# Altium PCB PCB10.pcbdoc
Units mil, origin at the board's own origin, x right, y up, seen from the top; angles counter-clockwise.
Board outline 2226.25 x 1287.2 mil, 2 copper layers (Top Layer, Bottom Layer); 3 components, 4 nets, 26 pads, 0 vias.
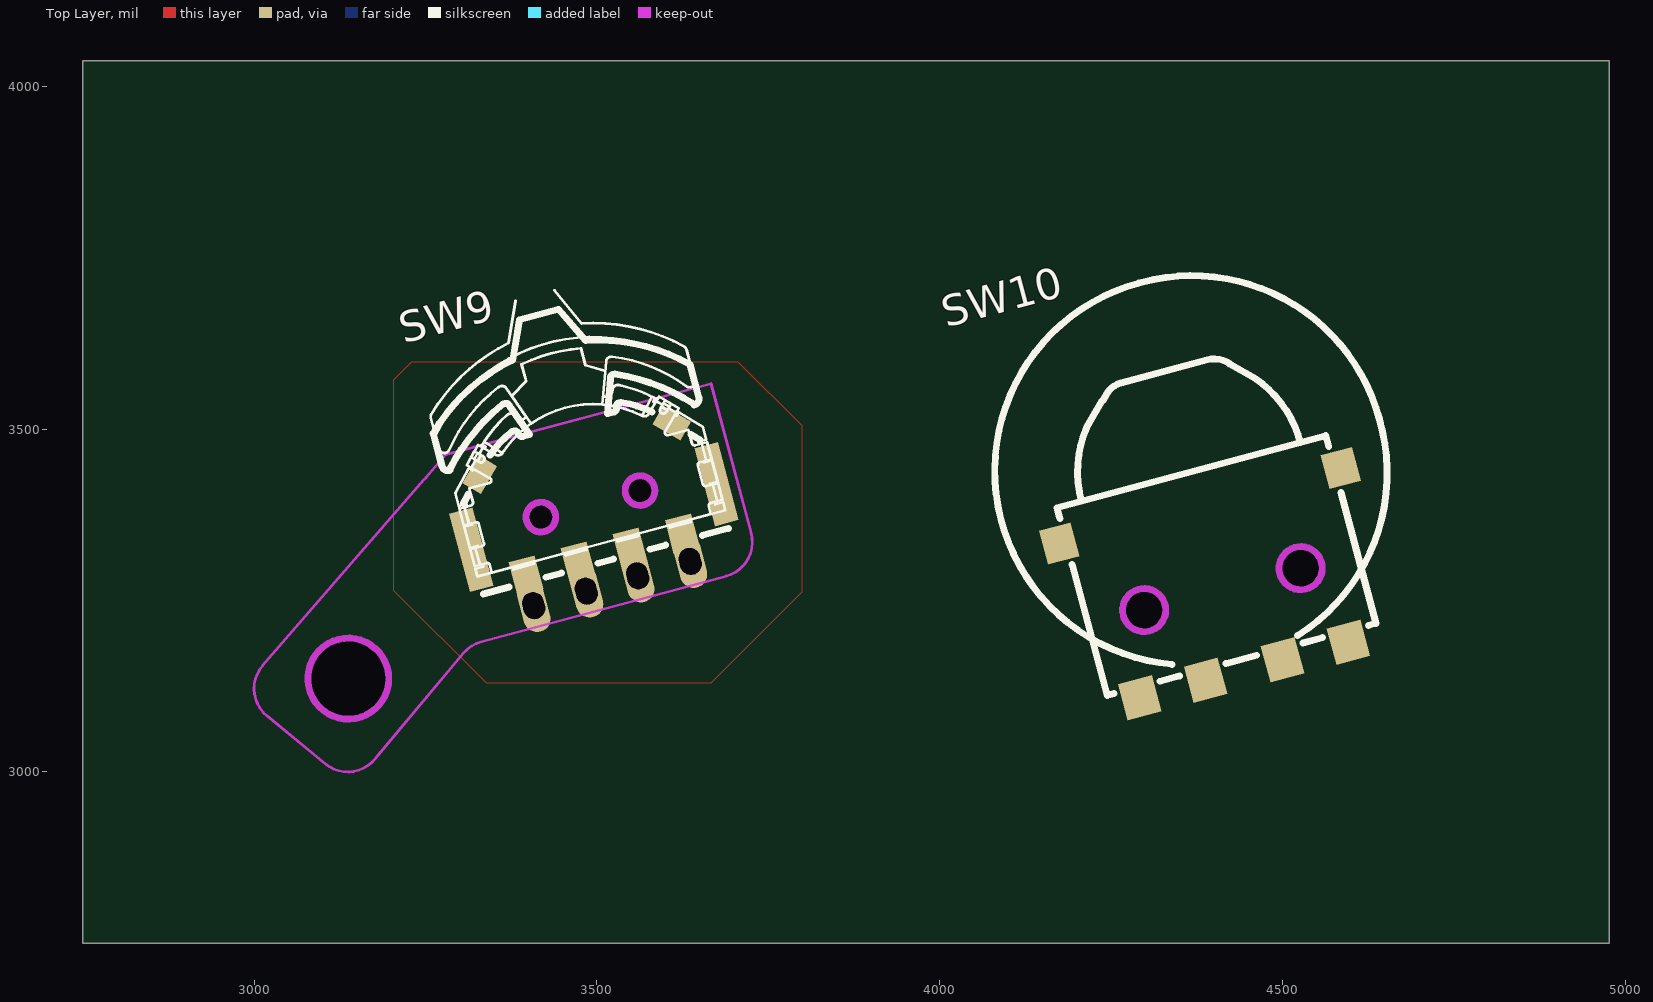
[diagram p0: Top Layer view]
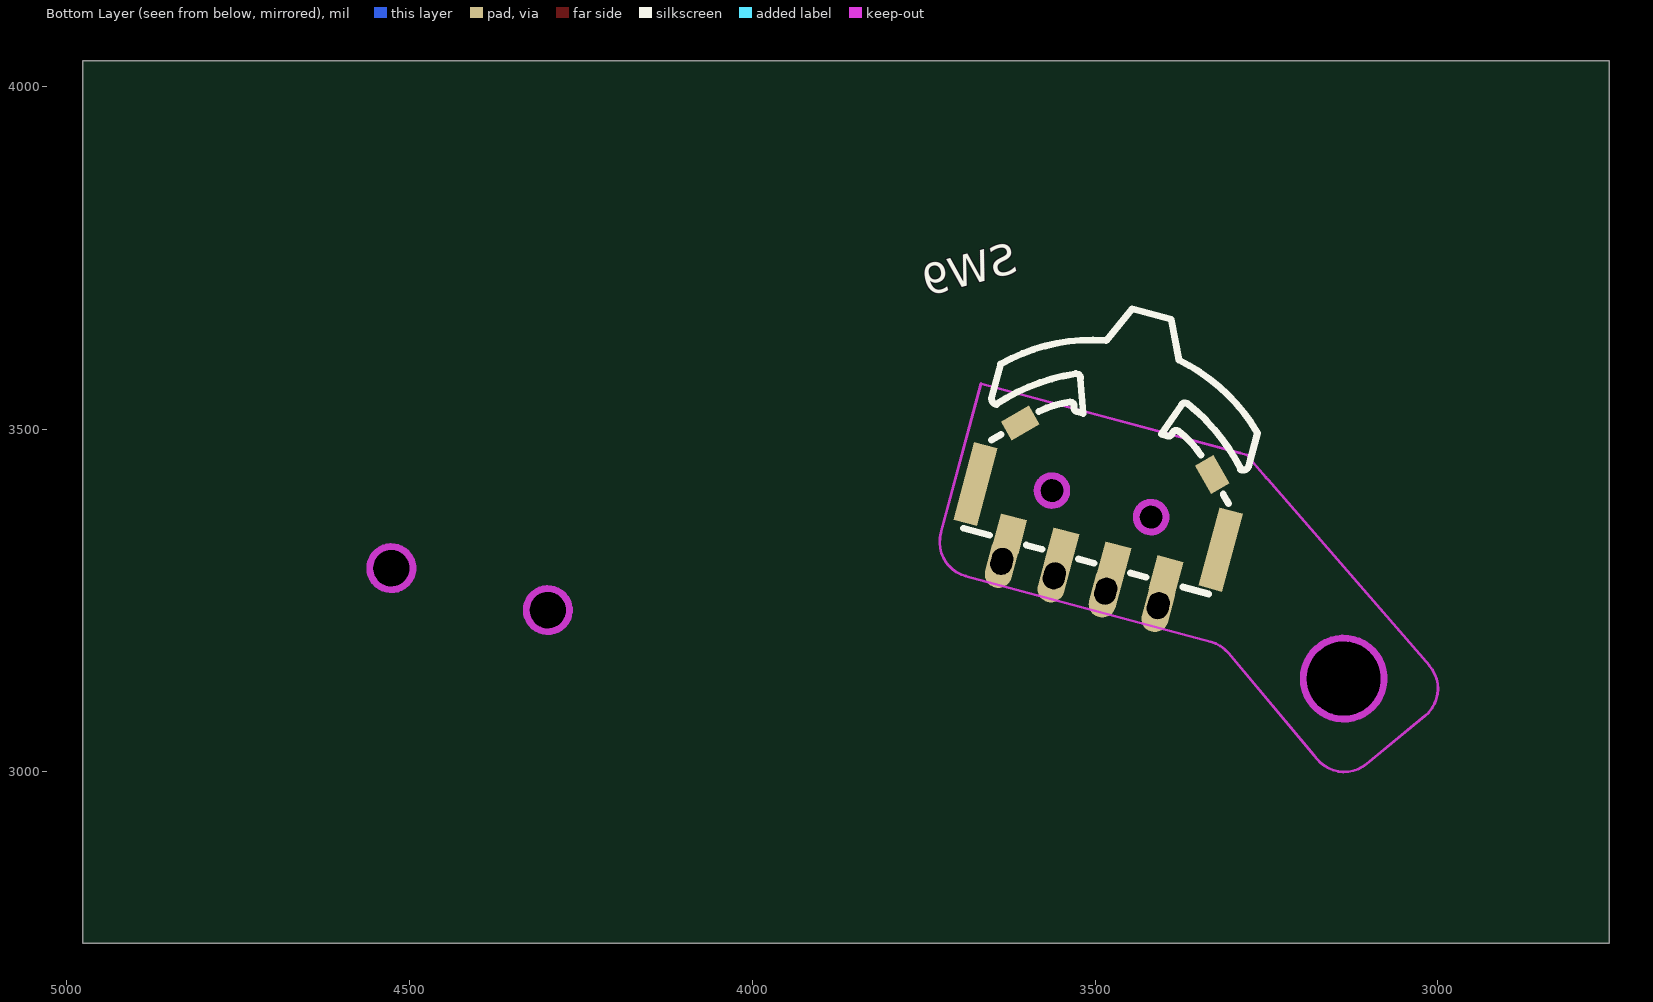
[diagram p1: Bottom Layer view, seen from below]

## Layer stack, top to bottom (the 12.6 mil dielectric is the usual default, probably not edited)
Top Layer: signal copper (thickness not stored)
Dielectric: dielectric 12.6, FR-4, Dk 4.8
Bottom Layer: signal copper (thickness not stored)

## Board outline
4976.25,2750 2750,2750 2750,4037.2 4976.25,4037.2
cut-out: 3196.46,3136.05 ccw(c3137.4,3135.79) 3078.35,3136.05 ccw(c3137.4,3136.31)

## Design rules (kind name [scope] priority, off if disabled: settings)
BoardOutlineClearance copperThickness1oz [All] p0: genericclearance=10 ignorepadtopadclearanceinfootprint=FALSE except(0: Arc-SplitContinuation Track-SplitContinuation SMDPad-SplitContinuation THPad-SplitContinuation Via-SplitContinuation Fill-SplitContinuation Poly-SplitContinuation Region-SplitContinuation Text-SplitContinuation; 6: SMDPad-CutoutEdge THPad-CutoutEdge Via-CutoutEdge Fill-CutoutEdge Region-CutoutEdge; 11.8: Track-OutlineEdge SMDPad-OutlineEdge THPad-OutlineEdge Via-OutlineEdge Fill-OutlineEdge Region-OutlineEdge Poly-OutlineEdge Text-OutlineEdge Track-CutoutEdge)
BoardOutlineClearance copperThickness2oz [All] p0: genericclearance=10 ignorepadtopadclearanceinfootprint=FALSE except(0: Arc-SplitContinuation Track-SplitContinuation SMDPad-SplitContinuation THPad-SplitContinuation Via-SplitContinuation Fill-SplitContinuation Poly-SplitContinuation Region-SplitContinuation Text-SplitContinuation; 6: SMDPad-CutoutEdge THPad-CutoutEdge Via-CutoutEdge Fill-CutoutEdge Region-CutoutEdge; 11.8: Track-OutlineEdge SMDPad-OutlineEdge THPad-OutlineEdge Via-OutlineEdge Fill-OutlineEdge Region-OutlineEdge Poly-OutlineEdge Text-OutlineEdge Track-CutoutEdge)
Clearance copperThickness1oz [(InNet('B5') OR InNet('GND') OR InNet('B3') OR InNet('B4'))] p1: gap=7 ignorepadtopadclearanceinfootprint=FALSE except(4: Track-Track; 6: Track-SMDPad SMDPad-SMDPad Track-THPad SMDPad-THPad THPad-THPad Track-Via SMDPad-Via THPad-Via Via-Via Track-Fill SMDPad-Fill THPad-Fill Via-Fill Fill-Fill SMDPad-Region THPad-Region Via-Region Fill-Region Region-Region Track-Poly SMDPad-Poly THPad-Poly Via-Poly Fill-Poly Poly-Poly Track-Text SMDPad-Text THPad-Text Via-Text Fill-Text Region-Text Poly-Text Text-Text Track-Hole SMDPad-Hole THPad-Hole Via-Hole Fill-Hole Region-Hole Poly-Hole Text-Hole; 11.8: Track-Region Region-Poly Track-Sheet SMDPad-Sheet THPad-Sheet Via-Sheet Fill-Sheet Region-Sheet Poly-Sheet Text-Sheet Sheet-Hole)
Clearance copperThickness2oz [All] p1: gap=7 ignorepadtopadclearanceinfootprint=FALSE except(6: Track-SMDPad SMDPad-SMDPad Track-THPad SMDPad-THPad THPad-THPad Track-Via SMDPad-Via THPad-Via Via-Via Track-Fill SMDPad-Fill THPad-Fill Via-Fill Fill-Fill SMDPad-Region THPad-Region Via-Region Fill-Region Region-Region Track-Poly SMDPad-Poly THPad-Poly Via-Poly Fill-Poly Poly-Poly Track-Text SMDPad-Text THPad-Text Via-Text Fill-Text Region-Text Poly-Text Text-Text Track-Hole SMDPad-Hole THPad-Hole Via-Hole Fill-Hole Region-Hole Poly-Hole Text-Hole; 8: Track-Track; 11.8: Track-Region Region-Poly Track-Sheet SMDPad-Sheet THPad-Sheet Via-Sheet Fill-Sheet Region-Sheet Poly-Sheet Text-Sheet Sheet-Hole)
DiffPairsRouting differentialPair [All] p1: maxuncoupledlength=10 minlimit=5.9843 maxlimit=5.9843 mostfreqgap=5.9843 toplayer_minwidth=5 toplayer_prefwidth=10 toplayer_maxwidth=100 bottomlayer_minwidth=5 bottomlayer_prefwidth=10 bottomlayer_maxwidth=100
PasteMaskExpansion pasteMaskExpansion [All] p1: expansion=0
PlaneConnect innerPlane [All] p1: planeconnectstyle=Relief reliefexpansion=20 reliefentries=4 reliefconductorwidth=10 reliefairgap=10
PolygonConnect copperRegion [All] p1: connectstyle=Direct reliefentries=4 reliefconductorwidth=10 polygonreliefangle="90 Angle" airgapwidth=10
RoutingVias viaSize [All] p1: viastyle="Through Hole" holewidth=12.0078 minholewidth=11.811 maxholewidth=248.0314 width=24.0158 minwidth=19.685 maxwidth=393.7008
SolderMaskExpansion solderMaskExpansion [All] p1: useseparateexpansions=TRUE expansion=2.0079 expansionbottom=2.0079
Width copperThickness1oz [All] p1: maxlimit=100 minlimit=5 preferedwidth=10
Width copperThickness2oz [All] p1: maxlimit=100 minlimit=8 preferedwidth=10

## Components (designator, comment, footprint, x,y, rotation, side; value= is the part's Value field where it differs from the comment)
SW9 "TM-2023" SW-SMD_TM-2023-1 3489.66,3393.93 r15 top
SW9 "TM-2023" SW-SMD_TM-2023-1 3489.68,3394 r195 bottom
SW10 "SIQ-02FVS3_2" SW-SMD_SIQ-02FVS3 4411.47,3268.43 r15 top

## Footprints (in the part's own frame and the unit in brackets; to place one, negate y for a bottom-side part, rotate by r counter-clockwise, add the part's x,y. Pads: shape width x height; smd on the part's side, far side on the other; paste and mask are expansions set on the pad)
SW-SMD_SIQ-02FVS3 [mm]
  rect 1.2x1.3 smd: 1(-5.4,3.15) 2(5.4,3.15)
  rect 1.3x1.4 smd: A(-4,-3.15) B(4,-3.15) C(1.475,-3.15) S(-1.475,-3.15)
  Board Outline Layer circle w0.005: c-3,-0.05 r0.8
  Board Outline Layer circle w0.005: c3,-0.05 r0.8
  Board Outline Layer circle w0.254: c-3,-0.05 r0.8
  Board Outline Layer circle w0.254: c3,-0.05 r0.8
  Multi-Layer board cut-out: -2.227,-0.257 -2.214,0.099 -2.356,0.425 -2.626,0.657 -2.97,0.749 -3.32,0.683 -3.606,0.472 -3.773,0.157 -3.773,0.157 -3.786,-0.199 -3.644,-0.525 -3.374,-0.757 -3.03,-0.85 -2.68,-0.783 -2.394,-0.572 -2.227,-0.257
  Multi-Layer board cut-out: 3.773,-0.257 3.786,0.099 3.644,0.425 3.374,0.657 3.03,0.749 2.68,0.683 2.393,0.472 2.227,0.157 2.227,0.157 2.227,-0.257 2.434,-0.616 2.793,-0.823 3.207,-0.823 3.566,-0.616 3.773,-0.257
  silkscreen extent -7.25,-2.75 7.25,11.7
SW-SMD_TM-2023-1 [mm]
  rect 1x1.3 smd: 1(-3,-2.03) 2(3,-2.03) C(-1,-2.03) T(1,-2.03)
  rect 0.9x3 smd: 3(-4.7,-0.58) 4(4.7,-0.58)
  rect 1.2x0.8 smd rot 135: 5(3.68,2.03)
  rect 1.2x0.8 smd rot 45: 6(-3.68,2.03)
  Board Outline Layer circle w0.005: c-1.9,-0.08 r0.55
  Board Outline Layer circle w0.005: c1.9,-0.08 r0.55
  Board Outline Layer circle w0.254: c-1.9,-0.08 r0.55
  Board Outline Layer circle w0.254: c1.9,-0.08 r0.55
  Multi-Layer board cut-out: -1.369,-0.223 -1.369,0.062 -1.511,0.309 -1.758,0.451 -2.043,0.451 -2.289,0.309 -2.431,0.062 -2.431,0.062 -2.441,-0.182 -2.343,-0.407 -2.157,-0.567 -1.921,-0.63 -1.68,-0.584 -1.483,-0.439 -1.369,-0.223
  Multi-Layer board cut-out: 2.431,-0.223 2.44,0.022 2.342,0.246 2.157,0.406 1.92,0.469 1.68,0.424 1.483,0.279 1.368,0.062 1.368,0.062 1.368,-0.223 1.511,-0.469 1.757,-0.612 2.042,-0.612 2.289,-0.469 2.431,-0.223
  silkscreen extent -4.95,-2.28 4.9,7.19

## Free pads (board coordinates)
  oval 78.74x39.37 hole 31.5 slot 39.37 at 105 deg rot 105: 9(3407.72,3242.53) 9(3484.39,3263.6) 9(3559.31,3285.84) 9(3635.98,3306.91)

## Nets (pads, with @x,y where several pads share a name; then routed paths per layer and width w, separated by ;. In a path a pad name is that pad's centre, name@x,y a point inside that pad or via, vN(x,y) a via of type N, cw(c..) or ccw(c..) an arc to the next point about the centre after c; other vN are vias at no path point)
B3: pad.9@3407.72,3242.53 SW9.1@3396.26,3286.16 SW9.2@3396.28,3286.22
B4: pad.9@3635.98,3306.91 SW9.1@3624.45,3347.36 SW9.2@3624.43,3347.3
B5: pad.9@3559.31,3285.84 SW9.C@3548.41,3326.99 SW9.T@3548.36,3326.91
GND: pad.9@3484.39,3263.6 SW9.3 SW9.4 SW9.5 SW9.6 SW9.C@3472.31,3306.53 SW9.T@3472.35,3306.61
pads on no net: SW10.1 SW10.2 SW10.A SW10.B SW10.C SW10.S

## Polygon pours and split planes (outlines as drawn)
GND on Top Layer (solid, remove dead copper, pour order 0): 3203.18,3571.4 3203.18,3265 3338.38,3129.81 3666.72,3129.81 3799.28,3262.37 3799.28,3504.68 3706.22,3597.73 3229.51,3597.73

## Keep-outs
Board Outline Layer:
  circle w1: c3137.4,3136.05 r59.05
  circle w10: c3137.4,3136.05 r59.05
  lines w3.94: 3288.46,3465 3666.33,3566.25 3724.74,3348.25 cw(c3675.3,3335.01) 3688.55,3285.57 3331.49,3189.9 ccw(c3344.74,3140.46) 3305.49,3173.31 3181.06,3024.68 3176.13,3018.68 cw(c3136.59,3051.18) 3104.09,3011.64 3018.68,3081.83 cw(c3051.18,3121.37) 3012.5,3154.89 3247.43,3426 3250.82,3428.47 3250.53,3429.58 3279.03,3462.47 3325.49,3474.92

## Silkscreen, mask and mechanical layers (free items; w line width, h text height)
Top Silkscreen Layer:
  drawing of 164 lines, arcs and shapes, not listed
Mechanical Layer:
  circle w1: c3137.4,3136.05 r59.05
